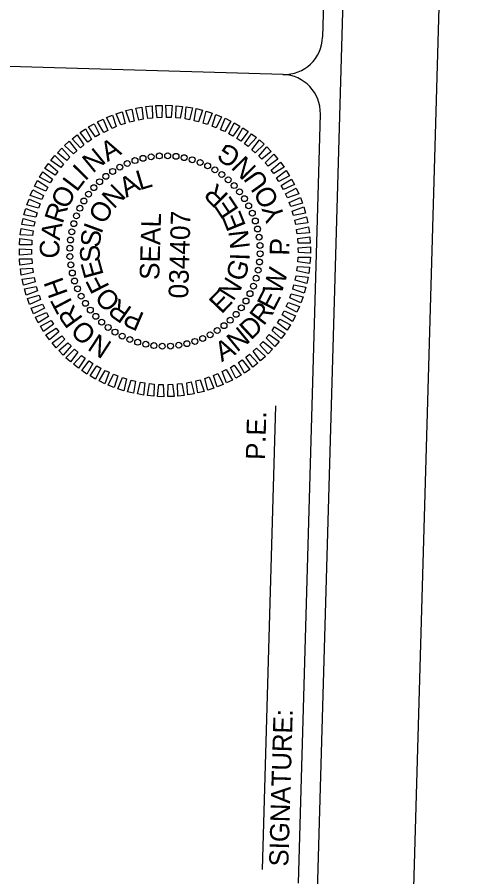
# Model space of a CAD drawing. Extents: x 2097846 to 2099709, y 989477 to 992073.
# Drawn here: x 2099395.9 to 2099568.5, y 991407.2 to 991742.1 of the extents above; entities that cross this region are included whole.
import ezdxf

# ---------------------------------------------------------------- set-up
doc = ezdxf.new("R2010")
doc.units = 0
for name, color, linetype in [('Sheet PE Seal Cell', 7, 'Continuous'), ('Sheet Title CELL', 7, 'Continuous'), ('Stewart Plot Border Xerox6279 and LJ5000', 7, 'Continuous')]:
    doc.layers.add(name, color=color, linetype=linetype)

msp = doc.modelspace()

# ---------------------------------------------------------------- linework, layer by layer
at = {"layer": 'Sheet PE Seal Cell'}
for points in [[(2099443.32, 991702.04), (2099442.11, 991706.66), (2099444.55, 991707.06), (2099445.04, 991702.37)], [(2099446.9, 991702.63), (2099446.01, 991707.32), (2099448.48, 991707.55), (2099448.64, 991702.83)], [(2099450.52, 991702.97), (2099449.96, 991707.71), (2099452.43, 991707.77), (2099452.26, 991703.05)], [(2099454.15, 991703.05), (2099453.92, 991707.82), (2099456.39, 991707.7), (2099455.89, 991703.01)], [(2099457.77, 991702.88), (2099457.88, 991707.65), (2099460.34, 991707.36), (2099459.51, 991702.72)], [(2099461.38, 991702.46), (2099461.82, 991707.21), (2099464.25, 991706.75), (2099463.1, 991702.17)], [(2099432.94, 991698.81), (2099430.79, 991703.07), (2099433.1, 991703.97), (2099434.55, 991699.48)], [(2099436.32, 991700.13), (2099434.48, 991704.53), (2099436.84, 991705.27), (2099437.98, 991700.69)], [(2099439.79, 991701.21), (2099438.25, 991705.73), (2099440.66, 991706.3), (2099441.48, 991701.65)], [(2099464.94, 991701.78), (2099465.72, 991706.49), (2099468.11, 991705.87), (2099466.65, 991701.38)], [(2099468.46, 991700.86), (2099469.55, 991705.51), (2099471.9, 991704.72), (2099470.12, 991700.34)], [(2099471.89, 991699.7), (2099473.31, 991704.26), (2099475.6, 991703.3), (2099473.52, 991699.06)], [(2099426.49, 991695.48), (2099423.77, 991699.4), (2099425.93, 991700.62), (2099427.99, 991696.37)], [(2099429.66, 991697.26), (2099427.22, 991701.36), (2099429.45, 991702.42), (2099431.22, 991698.04)], [(2099475.24, 991698.3), (2099476.98, 991702.75), (2099479.19, 991701.64), (2099476.82, 991697.55)], [(2099478.49, 991696.67), (2099480.53, 991700.98), (2099482.66, 991699.72), (2099480.01, 991695.81)], [(2099423.46, 991693.48), (2099420.47, 991697.21), (2099422.54, 991698.57), (2099424.89, 991694.48)], [(2099481.61, 991694.81), (2099483.95, 991698.98), (2099485.98, 991697.57), (2099483.07, 991693.86)], [(2099484.59, 991692.75), (2099487.22, 991696.74), (2099489.15, 991695.19), (2099485.99, 991691.69)], [(2099417.84, 991688.89), (2099414.37, 991692.16), (2099416.22, 991693.8), (2099419.13, 991690.07)], [(2099420.57, 991691.28), (2099417.33, 991694.79), (2099419.3, 991696.29), (2099421.93, 991692.38)], [(2099487.43, 991690.48), (2099490.32, 991694.28), (2099492.14, 991692.6), (2099488.74, 991689.33)], [(2099415.29, 991686.31), (2099411.59, 991689.33), (2099413.33, 991691.09), (2099416.49, 991687.58)], [(2099490.1, 991688.02), (2099493.25, 991691.61), (2099494.94, 991689.81), (2099491.33, 991686.78)], [(2099412.92, 991683.55), (2099409.02, 991686.31), (2099410.64, 991688.19), (2099414.03, 991684.91)], [(2099492.59, 991685.38), (2099495.98, 991688.74), (2099497.55, 991686.82), (2099493.73, 991684.05)], [(2099410.75, 991680.64), (2099406.67, 991683.12), (2099408.15, 991685.11), (2099411.76, 991682.07)], [(2099494.89, 991682.57), (2099498.51, 991685.68), (2099499.94, 991683.66), (2099495.93, 991681.17)], [(2099408.79, 991677.59), (2099404.55, 991679.78), (2099405.88, 991681.86), (2099409.7, 991679.08)], [(2099496.98, 991679.6), (2099500.81, 991682.46), (2099502.1, 991680.35), (2099497.93, 991678.13)], [(2099407.05, 991674.4), (2099402.66, 991676.29), (2099403.85, 991678.46), (2099407.85, 991675.96)], [(2099498.87, 991676.5), (2099502.89, 991679.08), (2099504.03, 991676.89), (2099499.71, 991674.97)], [(2099405.53, 991671.1), (2099401.03, 991672.68), (2099402.06, 991674.93), (2099406.22, 991672.71)], [(2099500.54, 991673.28), (2099504.73, 991675.57), (2099505.7, 991673.3), (2099501.27, 991671.69)], [(2099404.25, 991667.71), (2099399.64, 991668.97), (2099400.52, 991671.28), (2099404.83, 991669.36)], [(2099501.97, 991669.94), (2099506.31, 991671.94), (2099507.13, 991669.61), (2099502.59, 991668.31)], [(2099403.21, 991664.23), (2099398.53, 991665.17), (2099399.24, 991667.54), (2099403.67, 991665.92)], [(2099503.17, 991666.52), (2099507.64, 991668.21), (2099508.29, 991665.82), (2099503.68, 991664.84)], [(2099402.41, 991660.69), (2099397.67, 991661.3), (2099398.22, 991663.71), (2099402.75, 991662.4)], [(2099504.13, 991663.02), (2099508.71, 991664.39), (2099509.19, 991661.96), (2099504.52, 991661.31)], [(2099401.86, 991657.1), (2099397.09, 991657.38), (2099397.47, 991659.82), (2099402.08, 991658.83)], [(2099504.84, 991659.46), (2099509.5, 991660.51), (2099509.82, 991658.05), (2099505.11, 991657.73)], [(2099505.31, 991655.86), (2099510.03, 991656.58), (2099510.17, 991654.11), (2099505.45, 991654.11)], [(2099401.57, 991653.48), (2099396.79, 991653.42), (2099396.99, 991655.89), (2099401.67, 991655.23)], [(2099401.52, 991649.85), (2099396.76, 991649.46), (2099396.79, 991651.93), (2099401.5, 991651.6)], [(2099505.52, 991652.23), (2099510.28, 991652.62), (2099510.25, 991650.15), (2099505.54, 991650.48)], [(2099401.73, 991646.23), (2099397.01, 991645.51), (2099396.87, 991647.97), (2099401.59, 991647.97)], [(2099505.47, 991648.6), (2099510.25, 991648.66), (2099510.05, 991646.19), (2099505.37, 991646.86)], [(2099402.19, 991642.63), (2099397.53, 991641.58), (2099397.22, 991644.03), (2099401.93, 991644.36)], [(2099505.18, 991644.98), (2099509.94, 991644.71), (2099509.57, 991642.26), (2099504.95, 991643.25)], [(2099402.91, 991639.07), (2099398.33, 991637.7), (2099397.85, 991640.12), (2099402.52, 991640.77)], [(2099504.63, 991641.39), (2099509.36, 991640.79), (2099508.82, 991638.37), (2099504.29, 991639.68)], [(2099403.86, 991635.57), (2099399.4, 991633.88), (2099398.74, 991636.26), (2099403.36, 991637.24)], [(2099503.83, 991637.85), (2099508.51, 991636.92), (2099507.8, 991634.55), (2099503.37, 991636.17)], [(2099405.06, 991632.14), (2099400.73, 991630.14), (2099399.91, 991632.48), (2099404.45, 991633.77)], [(2099502.79, 991634.38), (2099507.39, 991633.12), (2099506.52, 991630.8), (2099502.21, 991632.73)], [(2099406.5, 991628.81), (2099402.31, 991626.51), (2099401.33, 991628.78), (2099405.77, 991630.39)], [(2099501.5, 991630.98), (2099506.01, 991629.4), (2099504.98, 991627.15), (2099500.81, 991629.37)], [(2099408.17, 991625.58), (2099404.15, 991623), (2099403.01, 991625.2), (2099407.33, 991627.11)], [(2099499.99, 991627.68), (2099504.37, 991625.79), (2099503.19, 991623.62), (2099499.19, 991626.13)], [(2099410.05, 991622.48), (2099406.22, 991619.62), (2099404.94, 991621.74), (2099409.11, 991623.95)], [(2099498.25, 991624.5), (2099502.49, 991622.31), (2099501.15, 991620.22), (2099497.34, 991623)], [(2099412.15, 991619.52), (2099408.53, 991616.4), (2099407.1, 991618.42), (2099411.11, 991620.92)], [(2099496.28, 991621.44), (2099500.37, 991618.96), (2099498.89, 991616.98), (2099495.28, 991620.01)], [(2099414.45, 991616.71), (2099411.06, 991613.35), (2099409.49, 991615.26), (2099413.31, 991618.03)], [(2099494.12, 991618.53), (2099498.01, 991615.77), (2099496.4, 991613.89), (2099493.01, 991617.18)], [(2099416.94, 991614.07), (2099413.79, 991610.48), (2099412.09, 991612.28), (2099415.71, 991615.31)], [(2099489.2, 991613.2), (2099492.67, 991609.92), (2099490.81, 991608.29), (2099487.91, 991612.01)], [(2099491.75, 991615.78), (2099495.44, 991612.75), (2099493.71, 991610.99), (2099490.55, 991614.5)], [(2099419.61, 991611.6), (2099416.72, 991607.81), (2099414.9, 991609.48), (2099418.3, 991612.76)], [(2099422.44, 991609.34), (2099419.82, 991605.34), (2099417.89, 991606.89), (2099421.05, 991610.39)], [(2099486.47, 991610.8), (2099489.71, 991607.29), (2099487.74, 991605.79), (2099485.11, 991609.71)], [(2099425.43, 991607.27), (2099423.09, 991603.1), (2099421.06, 991604.51), (2099423.97, 991608.23)], [(2099428.55, 991605.42), (2099426.51, 991601.1), (2099424.38, 991602.36), (2099427.03, 991606.27)], [(2099480.55, 991606.61), (2099483.27, 991602.68), (2099481.11, 991601.47), (2099479.04, 991605.71)], [(2099483.58, 991608.6), (2099486.57, 991604.87), (2099484.5, 991603.51), (2099482.14, 991607.6)], [(2099431.79, 991603.79), (2099430.06, 991599.34), (2099427.85, 991600.45), (2099430.21, 991604.53)], [(2099435.14, 991602.39), (2099433.72, 991597.83), (2099431.44, 991598.78), (2099433.51, 991603.02)], [(2099474.1, 991603.28), (2099476.25, 991599.01), (2099473.94, 991598.11), (2099472.49, 991602.6)], [(2099477.38, 991604.83), (2099479.82, 991600.72), (2099477.58, 991599.66), (2099475.82, 991604.04)], [(2099438.58, 991601.22), (2099437.48, 991596.57), (2099435.14, 991597.37), (2099436.91, 991601.74)], [(2099442.09, 991600.3), (2099441.32, 991595.59), (2099438.93, 991596.22), (2099440.39, 991600.7)], [(2099445.66, 991599.63), (2099445.22, 991594.87), (2099442.79, 991595.33), (2099443.94, 991599.91)], [(2099449.27, 991599.2), (2099449.16, 991594.43), (2099446.7, 991594.72), (2099447.53, 991599.37)], [(2099460.14, 991599.45), (2099461.02, 991594.76), (2099458.56, 991594.53), (2099458.4, 991599.25)], [(2099463.72, 991600.04), (2099464.93, 991595.42), (2099462.49, 991595.02), (2099462, 991599.72)], [(2099467.25, 991600.88), (2099468.78, 991596.35), (2099466.38, 991595.78), (2099465.56, 991600.43)], [(2099470.72, 991601.96), (2099472.56, 991597.55), (2099470.2, 991596.82), (2099469.06, 991601.4)], [(2099452.89, 991599.03), (2099453.12, 991594.26), (2099450.65, 991594.38), (2099451.15, 991599.07)], [(2099456.52, 991599.12), (2099457.08, 991594.37), (2099454.61, 991594.32), (2099454.78, 991599.03)]]:
    msp.add_lwpolyline(points, close=True, dxfattribs=at)
for centre in [(2099441.84, 991686.26), (2099444.95, 991687.15), (2099448.13, 991687.75), (2099451.35, 991688.08), (2099454.59, 991688.13), (2099457.82, 991687.9), (2099461.01, 991687.38), (2099464.15, 991686.59), (2099467.21, 991685.53), (2099433.12, 991682.04), (2099435.9, 991683.7), (2099438.81, 991685.11), (2099470.16, 991684.21), (2099472.99, 991682.63), (2099430.5, 991680.14), (2099475.67, 991680.81), (2099478.18, 991678.77), (2099425.79, 991675.7), (2099428.05, 991678.02), (2099480.5, 991676.51), (2099423.75, 991673.19), (2099482.62, 991674.06), (2099421.93, 991670.51), (2099484.51, 991671.44), (2099486.17, 991668.66), (2099420.36, 991667.69), (2099487.59, 991665.75), (2099419.03, 991664.73), (2099488.74, 991662.72), (2099417.18, 991658.53), (2099417.97, 991661.67), (2099489.62, 991659.61), (2099416.66, 991655.34), (2099490.23, 991656.43), (2099416.43, 991652.11), (2099490.56, 991653.21), (2099416.48, 991648.87), (2099490.61, 991649.97), (2099416.81, 991645.65), (2099490.38, 991646.74), (2099417.42, 991642.47), (2099489.86, 991643.55), (2099418.3, 991639.36), (2099489.07, 991640.41), (2099419.45, 991636.34), (2099488.01, 991637.35), (2099420.86, 991633.42), (2099486.68, 991634.4), (2099422.52, 991630.64), (2099483.29, 991628.89), (2099485.11, 991631.57), (2099424.42, 991628.02), (2099426.54, 991625.57), (2099481.25, 991626.38), (2099428.86, 991623.32), (2099476.54, 991621.94), (2099478.99, 991624.06), (2099431.37, 991621.27), (2099434.05, 991619.45), (2099471.14, 991618.39), (2099473.92, 991620.05), (2099436.88, 991617.88), (2099439.83, 991616.55), (2099442.89, 991615.49), (2099465.2, 991615.82), (2099468.23, 991616.97), (2099446.03, 991614.7), (2099449.22, 991614.19), (2099452.45, 991613.95), (2099455.69, 991614), (2099458.91, 991614.33), (2099462.09, 991614.94)]:
    msp.add_circle(centre, 1.15, dxfattribs=at)
at = {"layer": 'Sheet Title CELL'}
for p, q in [((2099499.62, 991719.78), (2099259.72, 991726.7)), ((2099491.53, 991410.11), (2099496.75, 991590.7))]:
    msp.add_line(p, q, dxfattribs=at)
for points in [[(2099465.57, 989755.3), (2099529.49, 991974.37)], [(2099515.05, 991734.35), (2099521.75, 991967.09)], [(2099505.56, 991404.83), (2099514.19, 991704.37)]]:
    msp.add_lwpolyline(points, dxfattribs=at)
for centre, start, end in [((2099499.97, 991734.79), 268.35, 358.35), ((2099499.11, 991704.8), 358.35, 88.35)]:
    msp.add_arc(centre, 15, start, end, dxfattribs=at)
at = {"layer": 'Stewart Plot Border Xerox6279 and LJ5000'}
msp.add_lwpolyline([(2099495.04, 989476.82), (2099568.48, 992025.76), (2097919.17, 992073.28), (2097845.72, 989524.34)], close=True, dxfattribs=at)

# ---------------------------------------------------------------- texts
at = {"layer": 'Sheet PE Seal Cell'}
for s, height, rotation, p in [('A', 7.65, 29.2095, (2099431.11, 991685.63)), ('N', 7.65, 39.4199, (2099425.34, 991681.11)), ('G', 7.65, 145.8841, (2099483.71, 991689.22)), ('N', 7.65, 134.5584, (2099489.61, 991683.48)), ('I', 7.65, 45.3599, (2099422.38, 991678.03)), ('L', 7.65, 52.825, (2099419.13, 991673.76)), ('A', 7.65, 30.0411, (2099438.47, 991671.72)), ('L', 7.65, 16.7052, (2099443.64, 991674.64)), ('U', 7.65, 125.511, (2099494.37, 991677.51)), ('N', 7.65, 45.0911, (2099433.61, 991667.1)), ('R', 7.65, 135.3925, (2099478.66, 991672.72)), ('O', 7.65, 63.5502, (2099415.51, 991666.96)), ('O', 7.65, 117.3023, (2099498.22, 991670.28)), ('R', 7.65, 71.7589, (2099413.62, 991661.37)), ('O', 7.65, 60.8999, (2099429.99, 991661.07)), ('E', 7.65, 123.6303, (2099482.55, 991667.14)), ('E', 7.65, 111.868, (2099485.22, 991660.88)), ('Y', 7.65, 107.7973, (2099500.44, 991663.57)), ('SEAL', 7.651, 88.3496, (2099451.28, 991639.67)), ('034407', 7.651, 88.3496, (2099462.55, 991632.45)), ('A', 7.65, 80.8063, (2099412.5, 991654.97)), ('I', 7.65, 69.6554, (2099428.74, 991657.38)), ('S', 7.65, 81.6143, (2099427.96, 991652.1)), ('N', 7.65, 96.818, (2099486.69, 991652.31)), ('C', 7.65, 90.3114, (2099412.41, 991648.14)), ('S', 7.65, 93.5733, (2099428.3, 991646.78)), ('P', 7.65, 88.507, (2099501.96, 991649.16)), ('.', 7.65, 91.828, (2099502.08, 991651.9)), ('E', 7.65, 105.3355, (2099429.69, 991641.73)), ('G', 7.65, 73.0125, (2099484.38, 991638.81)), ('I', 7.65, 88.0625, (2099486.5, 991647.25)), ('W', 7.65, 72.8155, (2099498.82, 991633.72)), ('H', 7.65, 109.9506, (2099415.78, 991634.49)), ('F', 7.65, 117.0135, (2099432.07, 991637.1)), ('N', 7.65, 57.9624, (2099480.15, 991631.22)), ('E', 7.65, 62.654, (2099495.83, 991627.23)), ('O', 7.65, 132.8222, (2099436.68, 991631.79)), ('E', 7.65, 46.2002, (2099475.55, 991626.21)), ('T', 7.65, 117.7398, (2099418.37, 991629.53)), ('R', 7.65, 125.9485, (2099421.8, 991624.73)), ('R', 7.65, 144.9217, (2099441.09, 991628.68)), ('R', 7.65, 52.9503, (2099492.01, 991621.6)), ('P', 7.65, 156.6839, (2099445.91, 991626.62)), ('O', 7.65, 136.6736, (2099427.25, 991619.29)), ('D', 7.65, 42.8353, (2099486.99, 991616.08)), ('N', 7.65, 39.3357, (2099481.6, 991611.39)), ('N', 7.65, 146.8841, (2099433.29, 991615.14)), ('A', 7.65, 28.4634, (2099475.64, 991607.68))]:
    msp.add_text(s, height=height, rotation=rotation, dxfattribs=at).set_placement(p)
at = {"layer": 'Sheet Title CELL'}
for s, p in [('P.E.', (2099492.52, 991569.58)), ('SIGNATURE:', (2099501.61, 991411.17))]:
    msp.add_text(s, height=7.499, rotation=88.35, dxfattribs=at).set_placement(p)

doc.saveas('drawing.dxf')
